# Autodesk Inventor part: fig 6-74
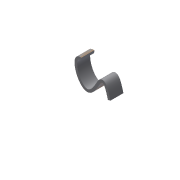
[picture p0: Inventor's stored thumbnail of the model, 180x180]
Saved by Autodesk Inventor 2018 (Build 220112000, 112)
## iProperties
Shininess: 64.0
Length Units: 11269
Angle Units: 11279
Time Units: 11290
Mass Units: 11283
Length Display Precision: 3
Angle Display Precision: 2
Compacted: True
Part Number: fig 6-74
Document SubType Name: Modeling
Created: 2002-12
Designer: deepak
Density: 1 g/cm^3
Material: Generic
Appearance: Default
Density: 0.0
Volumn: 0.0
Area: 0.0
PropertySet Name: Model Information
Control State: 0
Master: False
Checked Out: False
Author: deepak
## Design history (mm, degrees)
sketch "Sketch1"
  geometry: 5 further points
  constraints: 5 other
extrude_surface "ExtrusionSrf1" sketch "Sketch1" dims "d0" = 20, "d1" = 0
thicken "Thicken2" dims "d6" = 4, "d7" = 4
body "Solid1"
body "Srf1"
